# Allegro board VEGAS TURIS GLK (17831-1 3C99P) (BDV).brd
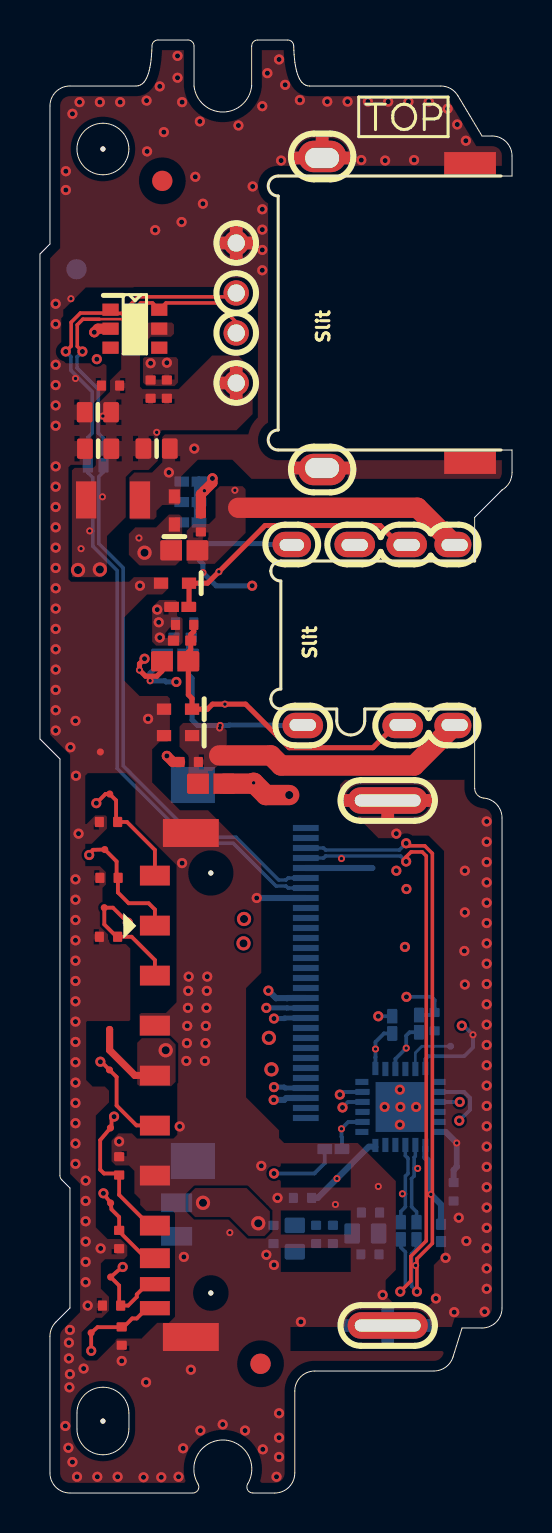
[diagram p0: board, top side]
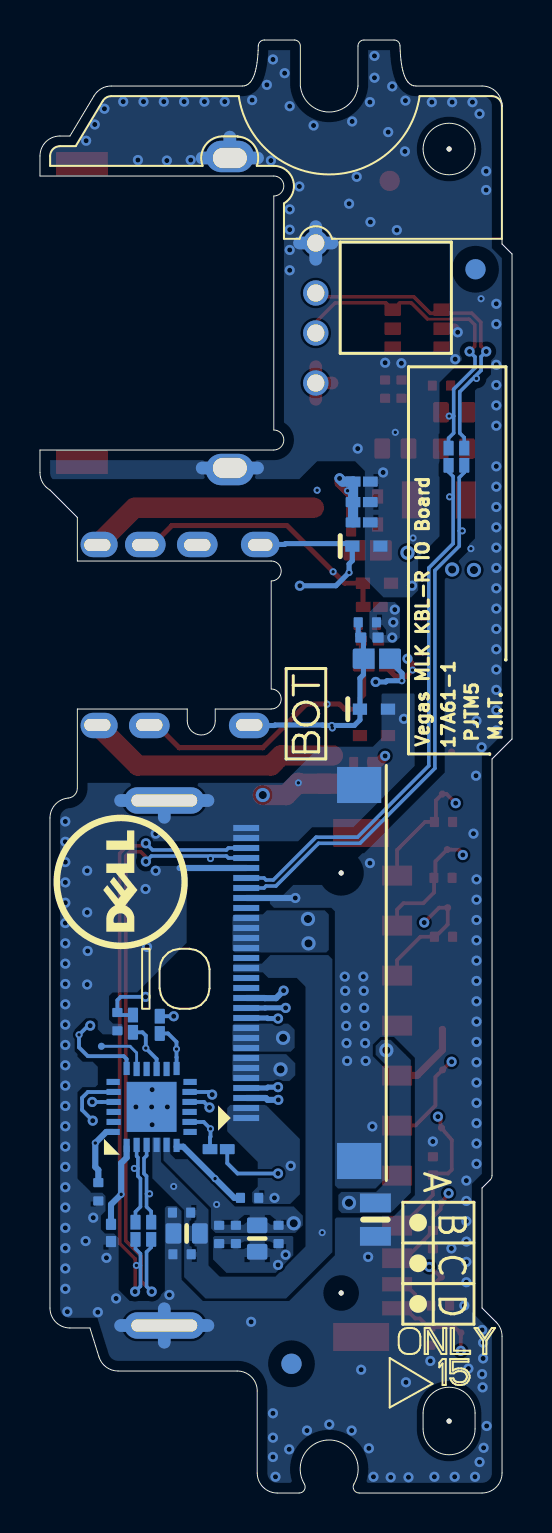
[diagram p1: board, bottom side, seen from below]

Outline 23.62 x 72.65 mm; copper layers: TOP, L2VCC, L3, L4, L5GND, BOTTOM. Coordinates in mm from the lower left corner of the outline.
Outline path: 0,61.95 0,37.7 1,36.7 1,15.87 arc(1.02,15.76) 1.09,15.66 1.5,15.25 1.5,9.25 0.79,8.54 arc(0.58,8.22) 0.5,7.84 0.5,1 arc(0.79,0.29) 1.5,0 7.65,0 arc(7.91,0.15) 7.91,0.45 arc(9.15,2.65) 10.39,0.45 arc(10.39,0.15) 10.65,0 11.75,0 arc(12.46,0.29) 12.75,1 12.75,5.1 arc(13.04,5.81) 13.75,6.1 19.71,6.1 arc(20.31,6.29) 20.67,6.8 21.12,8.25 22.12,8.25 arc(22.83,8.54) 23.12,9.25 23.12,33.75 arc(22.86,34.43) 22.21,34.75 arc(21.88,34.91) 21.75,35.24 21.75,39.2 16.25,39.2 16.25,38.6 arc(15.55,37.9) 14.85,38.6 14.85,39.2 12.05,39.2 arc(11.55,39.7) 12.05,40.2 12.05,45.6 arc(11.55,46.1) 12.05,46.6 21.75,46.6 21.75,48.78 23.12,50.15 arc(23.49,50.52) 23.62,51.02 23.62,52.15 11.92,52.15 arc(11.42,52.65) 11.92,53.15 11.92,64.85 arc(11.42,65.35) 11.92,65.85 23.62,65.85 23.62,66.85 arc(23.33,67.56) 22.62,67.85 22.12,67.85 20.91,69.86 arc(20.55,70.22) 20.05,70.35 13.49,70.35 13.38,70.36 13.28,70.4 13.19,70.45 13.11,70.53 13.04,70.62 12.98,70.71 12.93,70.82 12.89,70.94 12.85,71.07 12.81,71.21 12.78,71.36 12.76,71.53 12.73,71.72 12.72,71.91 12.7,72.13 12.7,72.36 arc(12.61,72.56) 12.4,72.65 10.89,72.65 arc(10.68,72.56) 10.59,72.35 10.59,70.35 arc(9.15,69.05) 7.71,70.35 7.71,72.35 arc(7.62,72.56) 7.41,72.65 5.9,72.65 arc(5.69,72.56) 5.6,72.36 5.59,72.1 5.58,71.86 5.56,71.65 5.53,71.45 5.5,71.27 5.46,71.11 5.42,70.97 5.38,70.85 5.33,70.74 5.28,70.64 5.21,70.55 5.13,70.47 5.03,70.4 4.92,70.36 4.81,70.35 1.5,70.35 arc(0.79,70.06) 0.5,69.35 0.5,62.45 0,61.95 ; 1.85,67.2 arc(3.15,68.5) 4.45,67.2 arc(3.15,65.9) 1.85,67.2 ; 1.85,4 arc(3.15,5.3) 4.45,4 4.45,3.2 arc(3.15,1.9) 1.85,3.2 1.85,4

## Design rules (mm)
constraint set DEFAULT: min track width 0.127, pair gap 0.102
net group SD_CLK: nets SD_CLK SD_CLK_5170
net group USB_PN2_C: nets USB_PN2_C USB_PN2_USB3
net group USB_PN5_C: nets USB_PN5_C USB_PN5_R
net group USB_PP2_C: nets USB_PP2_C USB_PP2_USB3
net group USB_PP5_C: nets USB_PP5_C USB_PP5_R
net group AUDIO-BEEP: nets AUD_PORTA_L_HPMIC1 AUD_PORTA_L_R_B AUD_PORTA_R_HPMIC1 AUD_PORTA_R_R_B JACK_PLUG JACK_PLUG_DET
net group CARD_12MIL: nets RREF SDREFG V18
net group CARD_READER_50R-MW: nets SD_CD# SD_CD_R# SD_CMD SD_WP SD_WP_5170
net group OTHER-MW: nets CR_GPIO0

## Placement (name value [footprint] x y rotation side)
AFTP201  AFTE14P-GP  [AFTE14P-75]  3.02 37.05 0 top
AFTP202  AFTE14P-GP  [AFTE14P-75]  3.22 29.26 0 top
AFTP203  AFTE14P-GP  [AFTE14P-75]  3.54 10.8 0 top
AFTP204  AFTE14P-GP  [AFTE14P-75]  3.48 21.16 0 top
AFTP205  AFTE14P-GP  [AFTE14P-75]  2.56 8.01 0 top
AFTP206  AFTE14P-GP  [AFTE14P-75]  3.53 18.25 0 top
AFTP207  AFTE14P-GP  [AFTE14P-75]  3.53 14.5 0 top
AFTP208  AFTE14P-GP  [AFTE14P-75]  3.49 34.95 0 top
AFTP209  AFTE14P-GP  [AFTE14P-75]  3.24 32.17 0 top
AFTP210  AFTE14P-GP  [AFTE14P-75]  3.48 23.18 0 top
C201  SCD1U16V2KX-3GP  [C402H22]  13.82 12.93 180 bottom
C202  SC1U10V2KX-1GP  [C402H22]  20.7 15.06 0 bottom
C203  SCD1U16V2KX-3GP  [C402H22]  14.66 12.93 180 bottom
C204  SC4D7U6D3V3KX-GP  [C603H36]  16.28 12.98 270 bottom
C205  SCD1U16V2KX-3GP  [C402H22]  16.53 14.02 270 bottom
C206  SC1U10V2KX-1GP  [C402H22]  13.13 14.76 90 bottom
C207  SC4D7U6D3V3KX-GP  [C603H36]  12.75 12.72 180 bottom
C208  SC10U10V5KX-2GP  [C805H54]  6.84 13.67 180 bottom
C301  SCD1U16V2KX-3GP  [C402H22]  6.35 55.19 180 top
C302  SC22U6D3V3MX-L1-GP  [C603H40]  2.89 54.04 270 top
C303  SC22U6D3V3MX-L1-GP  [C603H40]  2.91 52.22 270 top
C304  SC100U6D3V6MX-GP  [C1206H71]  3.66 49.66 90 top
C305  SC22U6D3V3MX-L1-GP  [C603H40]  5.84 52.22 90 top
C306  SCD1U16V2KX-3GP  [C402H22]  3.53 55.37 270 top
CARD1  SDCARD-11P-21-GP  [PSDATP-11GLBS1NN4H0]  8.55 21.5 90 top
EC201  SCD1U16V2KX-3GP  [C402H22]  16.51 11.94 270 bottom
EC202  SCD1U16V2KX-3GP  [C402H22]  11.68 12.93 180 bottom
EC203  SC6D8P50V2CN-GP  [C402H22]  3.96 16.36 180 top
EC204  SC6D8P50V2CN-GP  [C402H22]  4.09 7.85 0 top
EC205  SC6D8P50V2CN-GP  [C402H22]  3.96 12.67 0 top
EC206  SC6D8P50V2CN-GP  [C402H22]  3.45 30.76 270 top
EC207  SC6D8P50V2CN-GP  [C402H22]  3.58 9.37 270 top
EC208  SC6D8P50V2CN-GP  [C402H22]  3.43 27.81 270 top
EC209  SC6D8P50V2CN-GP  [C402H22]  3.43 33.55 270 top
EC210  SC6D8P50V2CN-GP  [C402H22]  19.75 23.57 180 bottom
EC301  SCD1U16V2KX-3GP  [C402H22]  5.54 55.19 180 top
EC402  SC680P50V2KX-2GP  [C402H22]  7.24 43.41 270 top
EC403  SC680P50V2KX-2GP  [C402H22]  7.24 43.53 90 bottom
EC404  SC680P50V2KX-2GP  [C402H22]  8.05 48.51 180 top
EC405  SC680P50V2KX-2GP  [C402H22]  7.47 36.55 270 top
ED401  AZ5125-01H-R7G-GP  [SOD-523-4H28]  6.72 49.13 180 top
ED402  AZ5125-01H-R7G-GP  [SOD-523-4H28]  6.76 45.49 270 top
ED403  AZ5125-01H-R7G-GP  [SOD-523-4H28]  7.29 47.34 90 bottom
ED404  AZ5125-01H-R7G-GP  [SOD-523-4H28]  6.91 37.87 270 top
ED405  AZ5125-01H-R7G-GP  [SOD-523-4H28]  6.91 39.19 90 bottom
ED406  AZ5125-01H-R7G-GP  [SOD-523-4H28]  6.91 39.19 270 top
EU301  AZC099-04S-2-GP  [SOT-6H58]  4.75 58.22 270 top
IOCN1  ACES-CON30-9-GP-U2  [51519-03001-W02-U2]  7.65 26 90 bottom
IUSB1  SKT-USB8-185-GP  [SKT-USB8-158161-4]  21.52 59 90 top
MIC1  AUDIO-JK554-GP  [2SJ3108-052111F]  20.75 42.9 90 top
NOREF  -  []  -201.05 -192.93 0 top
NOREF#2  -  []  -239.92 -205.64 0 top
NOREF#3  -  []  18.19 68.81 0 top
NOREF#4  *  [unnamed#2]  6.12 65.61 0 top
NOREF#5  -  [unnamed#2]  3.15 67.2 0 top
NOREF#6  *  [unnamed#2]  11.04 6.46 0 top
NOREF#7  -  []  -15.85 89 0 top
NOREF#8  -  []  -202.67 -192.25 0 top
NOREF#9  -  [unnamed#2]  3.15 3.59 0 top
NOREF#10  -  []  -202.67 -192.25 0 top
NOREF#11  *  [unnamed#2]  11.04 6.46 180 bottom
NOREF#12  -  []  10.31 38.96 90 bottom
NOREF#13  -  []  19.58 30.55 90 bottom
NOREF#14  -  []  383.93 -192.25 180 bottom
NOREF#15  -  []  374.89 -205.64 180 bottom
NOREF#16  *  [unnamed#2]  1.83 61.19 180 bottom
NOREF#17  -  []  321.64 -192.93 180 bottom
NOREF#18  -  []  5.82 59.76 180 bottom
NOREF#19  -  []  3.18 10.72 270 bottom
R201  -  [0R0402-PAD]  18.06 13.11 0 bottom
R202  6K2R2F-GP  [R402H16]  20.07 13 180 bottom
R203  -  [0R0402-PAD]  18.84 13.11 0 bottom
R204  -  [0R0402-PAD]  14.68 17.19 270 bottom
R205  -  [0R0402-PAD]  17.63 23.41 180 bottom
R206  -  [0R0402-PAD]  18.97 23.47 0 bottom
R301  -  [0R0402-PAD]  3.18 51.81 180 bottom
R302  -  [0R0402-PAD]  2.39 51.81 180 bottom
R424  -  [0R0603-PAD]  8.56 35.47 270 top
R426  -  [0R0603-PAD]  6.76 41.59 90 top
R427  -  [0R0603-PAD]  7.22 47.13 90 top
R428  10KR2J-3-GP  [R402H16]  7.11 42.62 270 top
R429  10KR2J-3-GP  [R402H16]  7.14 42.77 90 bottom
R430  -  [0R0402-PAD]  7.01 44.3 270 top
R431  -  [0R0402-PAD]  7.52 48.53 90 bottom
R432  -  [0R0402-PAD]  7.52 49.55 90 bottom
R433  -  [0R0402-PAD]  7.52 50.57 90 bottom
R434  -  [0R0603-PAD]  6.76 41.71 270 bottom
TP201  TPAD14-OP-GP  [TPAD14-OP]  20.54 22.34 180 bottom
U201  RTS5170-GR-GP  [QFN24-G2D5H40-U]  18.03 19.3 0 bottom

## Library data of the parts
AFTP201-AFTP210 = AFTE14P-75: tolerance: ZZ.AFT14.101
C201 C203 C205 C301 C306 EC201 EC202 EC301 = C402H22: tolerance: 78.10421.2FL
C202 C206 = C402H22: tolerance: 78.10523.5FL
C204 C207 = C603H36: tolerance: 78.47520.5BL
C208 = C805H54: tolerance: 78.10623.51L
C302 C303 C305 = C603H40: tolerance: 78.22610.L4L
C304 = C1206H71: tolerance: 78.10710.52L
CARD1 = PSDATP-11GLBS1NN4H0: tolerance: 062.10002.0491
EC203-EC210 = C402H22: tolerance: 78.6R874.1FL
EC402-EC405 = C402H22: tolerance: 78.68124.2FL
ED401-ED406 = SOD-523-4H28: tolerance: 75.05125.070
EU301 = SOT-6H58: tolerance: 075.09904.0A7C
IOCN1 = 51519-03001-W02-U2: tolerance: 20.K0510.030
IUSB1 = SKT-USB8-158161-4: tolerance: 022.10005.0821
MIC1 = 2SJ3108-052111F: tolerance: 022.10002.0G81
R201 = 0R0402-PAD: tolerance: ZZ.R0402.ZZZ; signal model: Graser_R201
R202 = R402H16: tolerance: 64.62015.6DL
R203 = 0R0402-PAD: tolerance: ZZ.R0402.ZZZ; signal model: Graser_R203
R204 R205 R430-R433 = 0R0402-PAD: tolerance: ZZ.R0402.ZZZ
R206 = 0R0402-PAD: tolerance: ZZ.R0402.ZZZ; signal model: Graser_R206
R301 = 0R0402-PAD: tolerance: ZZ.R0402.ZZZ; signal model: Graser_R301
R302 = 0R0402-PAD: tolerance: ZZ.R0402.ZZZ; signal model: Graser_R302
R424 R426 R427 R434 = 0R0603-PAD: tolerance: ZZ.R0603.ZZZ
R428 R429 = R402H16: tolerance: 63.10334.1DL
TP201 = TPAD14-OP: tolerance: ZZ.PAD14.001
U201 = QFN24-G2D5H40-U: tolerance: 71.05170.003

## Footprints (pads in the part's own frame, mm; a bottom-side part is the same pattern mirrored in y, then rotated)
0R0402-PAD
  custom 0.127x0.127 smd: 1(0,0.432) 2(0,-0.432)
0R0603-PAD
  custom 0.254x0.254 smd: 1(0,0.66) 2(0,-0.66)
2SJ3108-052111F
  oval 1.27x2.032 hole 0.61x1.321: 1(-4.5,7.6) 2(-4.5,2.6) 6(4.5,2.4) MS(4.5,5)
  oval 1.27x1.854 hole 0.61x1.321: 3(-4.5,0) 4(4.5,0)
  oval 1.27x1.93 hole 0.61x1.219: 5(4.5,8.15)
51519-03001-W02-U2
  rect 0.305x1.295 smd: 1(-7.25,5.65) 2(-6.75,5.65) 3(-6.25,5.65) 4(-5.75,5.65) 5(-5.25,5.65) 6(-4.75,5.65) 7(-4.25,5.65) 8(-3.75,5.65) 9(-3.25,5.65) 10(-2.75,5.65) 11(-2.25,5.65) 12(-1.75,5.65) 13(-1.25,5.65) 14(-0.75,5.65) 15(-0.25,5.65) 16(0.25,5.65) 17(0.75,5.65) 18(1.25,5.65) 19(1.75,5.65) 20(2.25,5.65) 21(2.75,5.65) 22(3.25,5.65) 23(3.75,5.65) 24(4.25,5.65) 25(4.75,5.65) 26(5.25,5.65) 27(5.75,5.65) 28(6.25,5.65) 29(6.75,5.65) 30(7.25,5.65)
  rect 1.803x2.21 smd: 31(-9.4,0) 32(9.4,0)
AFTE14P-75
  round 0.356 smd: 1(0,0)
C402H22
  custom 0.114x0.114 smd: 1(0,0.457) 2(0,-0.457)
C603H36
  custom 0.197x0.197 smd: 1(0,0.66) 2(0,-0.66)
C603H40
  custom 0.197x0.197 smd: 1(0,0.66) 2(0,-0.66)
C805H54
  rect 1.549x0.94 smd: 1(0,0.838) 2(0,-0.838)
C1206H71
  rect 1.854x1.016 smd: 1(0,1.346) 2(0,-1.346)
PSDATP-11GLBS1NN4H0
  round 0.254 hole 1.168 unplated: (-11.5,0)
  round 0.254 hole 1.651 unplated: (9.5,0)
  rect 0.991x1.499 smd: 1(6.87,2.8) 2(4.37,2.8) 3(1.87,2.8) 4(-0.63,2.8) 5(-3.13,2.8) 6(-5.63,2.8) 7(-8.13,2.8) 8(-9.76,2.8) 9(9.37,2.8)
  rect 0.711x1.499 smd: 10(-11.06,2.8) 11(-12.26,2.8)
  rect 1.397x2.794 smd: 12(11.5,1) 13(-13.7,1)
  oval 1.321x4.013 hole 0.61x3.302: 14(13.125,-8.85) 15(-13.125,-8.85)
QFN24-G2D5H40-U
  rect 0.305x0.66 smd: 1(1.25,1.987) 6(-1.25,1.987) 13(-1.25,-1.987) 18(1.25,-1.987)
  rect 0.305x0.711 smd: 2(0.75,1.962) 3(0.25,1.962) 4(-0.25,1.962) 5(-0.75,1.962) 14(-0.75,-1.962) 15(-0.25,-1.962) 16(0.25,-1.962) 17(0.75,-1.962)
  rect 0.66x0.305 smd: 7(-1.987,1.25) 12(-1.987,-1.25) 19(1.987,-1.25) 24(1.987,1.25)
  rect 0.711x0.305 smd: 8(-1.962,0.75) 9(-1.962,0.25) 10(-1.962,-0.25) 11(-1.962,-0.75) 20(1.962,-0.75) 21(1.962,-0.25) 22(1.962,0.25) 23(1.962,0.75)
  rect 2.489x2.489 smd: 25(0,0)
R402H16
  custom 0.127x0.127 smd: 1(0,0.432) 2(0,-0.432)
SKT-USB8-158161-4
  round 1.27 hole 0.864: 1(-3.5,11.7) 2(-1,11.7) 3(1,11.7) 4(3.5,11.7)
  oval 1.575x2.413 hole 1.016x1.702: 5(-7.75,7.4) 6(7.75,7.4)
  rect 1.194x2.591 smd: 7(-7.45,0) 8(7.45,0)
SOD-523-4H28
  rect 0.559x0.711 smd: 1(0,0.702) 2(0,-0.702)
SOT-6H58
  rect 0.61x0.813 smd: 1(-0.95,-1.219) 2(0,-1.219) 3(0.95,-1.219) 4(0.95,1.219) 5(0,1.219) 6(-0.95,1.219)
TPAD14-OP
  round 0.356 smd: 1(0,0)
unnamed#2
  round 1.016 smd: (0,0)

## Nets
GND: AFTP201.1 C201.2 C202.1 C203.2 C204.2 C205.2 C206.2 C207.2 C208.2 C301.2 C302.2 C303.2 C304.2 C305.2 C306.2 CARD1.3 CARD1.6 CARD1.12 CARD1.13 CARD1.14 CARD1.15 EC201.2 EC202.2 EC203.2 EC204.2 EC205.2 EC206.2 EC207.2 EC208.2 EC209.2 EC210.2 EC301.2 ED401.2 ED402.2 ED403.2 ED404.2 ED405.2 ED406.2 EU301.2 IOCN1.1 IOCN1.2 IOCN1.23 IOCN1.26 IOCN1.29 IOCN1.30 IOCN1.31 IOCN1.32 IUSB1.4 IUSB1.5 IUSB1.6 IUSB1.7 IUSB1.8 R202.2 R431.2 R432.2 R433.2 U201.25
V18: C202.2 U201.24
3D3V_CARD_S0: AFTP210.1 C201.1 C203.1 C207.1 C208.1 CARD1.4 EC202.1 U201.5
3D3V_S0: C204.1 C205.1 EC201.1 IOCN1.16 U201.4
AUD_AGND: EC402.2 EC403.2 EC404.2 EC405.2 IOCN1.3 IOCN1.13 MIC1.MS R428.2 R429.2 R430.2 R431.1 R432.1 R433.1
AUD_PORTA_L_HPMIC1: EC403.1 ED405.1 MIC1.1 R429.1 R434.2
AUD_PORTA_L_R_B: IOCN1.12 R434.1
AUD_PORTA_R_HPMIC1: EC402.1 ED406.1 MIC1.2 R426.2 R428.1
AUD_PORTA_R_R_B: IOCN1.11 R426.1
CR_GPIO0: TP201.1 U201.17
JACK_PLUG: ED403.1 IOCN1.4 MIC1.5
JACK_PLUG_DET: ED402.1 MIC1.6 R430.1
RING2_HPMIC1: EC405.1 ED404.1 MIC1.3 R424.2
RING2_R: IOCN1.5 IOCN1.6 IOCN1.7 R424.1
RREF: R202.1 U201.1
SD_CD#: R205.2 U201.13
SD_CD_R#: AFTP203.1 CARD1.10 EC207.1 R205.1
SD_CLK: AFTP204.1 CARD1.5 EC210.1 R206.2
SD_CLK_5170: R206.1 U201.15
SD_CMD: AFTP202.1 CARD1.2 EC208.1 U201.18
SD_D0: AFTP206.1 CARD1.7 EC203.1 U201.11
SD_D1: AFTP207.1 CARD1.8 EC205.1 U201.10
SD_D2: AFTP208.1 CARD1.9 EC209.1 U201.21
SD_D3: AFTP209.1 CARD1.1 EC206.1 U201.20
SD_WP: AFTP205.1 CARD1.11 EC204.1 R204.1
SD_WP_5170: R204.2 U201.8
SDREFG: C206.1 U201.6
SLEEVE_HPMIC1: EC404.1 MIC1.4 R427.2
SLEEVE_R: ED401.1 IOCN1.8 IOCN1.9 IOCN1.10 R427.1
USB20_VCCA: C301.1 C302.1 C303.1 C304.1 C305.1 C306.1 EC301.1 EU301.5 IOCN1.18 IOCN1.19 IOCN1.20 IOCN1.21 IUSB1.1
USB_PN2_C: IOCN1.25 R301.2
USB_PN2_USB3: EU301.6 IUSB1.2 R301.1
USB_PN5_C: IOCN1.28 R203.1
USB_PN5_R: R203.2 U201.2
USB_PP2_C: IOCN1.24 R302.2
USB_PP2_USB3: EU301.1 IUSB1.3 R302.1
USB_PP5_C: IOCN1.27 R201.1
USB_PP5_R: R201.2 U201.3

Pads without a net: EU301 3 4; IOCN1 14 15 17 22; U201 7 9 12 14 16 19 22 23

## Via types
v1: diameter 0.356, hole 0.178, TOP to BOTTOM, 32 vias
v2: diameter 0.711, hole 0.406, TOP to BOTTOM, 11 vias
v3: diameter 0.508, hole 0.254, TOP to BOTTOM, 225 vias

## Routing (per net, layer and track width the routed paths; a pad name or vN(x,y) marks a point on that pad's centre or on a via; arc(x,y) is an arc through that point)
GND: length 83.6
  TOP w0.508: EU301.2 2.9,58.22 v3(2.72,58.04)
  TOP w0.635: 15.22,34.63 CARD1.14 ; CARD1.14 19.58,34.63 ; CARD1.14 17.4,33.79 ; IUSB1.6 15.5,66.75 ; IUSB1.6 12.74,66.75 ; IUSB1.6 14.12,67.79 ; 12.74,51.25 IUSB1.5 15.5,51.25 ; 9.82,61.69 IUSB1.4 ; IUSB1.4 10.63,62.5 ; IUSB1.4 9.01,62.5 ; IUSB1.4 9.82,63.31
  L3 w0.635: 15.22,8.38 CARD1.15 ; CARD1.15 17.4,7.54 ; CARD1.15 17.4,9.21 ; CARD1.15 19.58,8.38 ; CARD1.14 17.4,35.46 ; CARD1.14 17.4,33.79 ; CARD1.14 15.22,34.63 ; CARD1.14 19.58,34.63 ; IUSB1.6 15.5,66.75 ; IUSB1.6 14.12,67.79 ; IUSB1.6 12.74,66.75 ; 9.82,61.69 IUSB1.4 ; IUSB1.4 9.01,62.5 ; IUSB1.4 10.63,62.5 ; IUSB1.4 9.82,63.31 ; 12.74,51.25 IUSB1.5 15.5,51.25
  L4 w0.635: IUSB1.4 10.63,62.5 ; IUSB1.4 9.82,61.69 ; IUSB1.4 9.82,63.31 ; IUSB1.4 9.01,62.5 ; IUSB1.6 14.12,67.79 ; IUSB1.6 15.5,66.75 ; IUSB1.6 12.74,66.75 ; 19.58,34.63 CARD1.14 17.4,33.79 ; CARD1.15 17.4,9.21 ; CARD1.15 17.4,7.54 ; CARD1.15 15.22,8.38 ; CARD1.15 19.58,8.38 ; 12.74,51.25 IUSB1.5 15.5,51.25
  BOTTOM w0.305: IOCN1.23 v3(10.85,29.75) ; IOCN1.26 16.64,31.25
  BOTTOM w0.635: 9.82,61.69 IUSB1.4 ; IUSB1.4 9.82,63.31 ; IUSB1.4 9.01,62.5 ; IUSB1.4 10.63,62.5 ; 12.74,66.75 IUSB1.6 ; IUSB1.6 14.12,67.79 ; IUSB1.6 15.5,66.75 ; 17.4,33.79 CARD1.14 ; CARD1.14 19.58,34.63 ; CARD1.14 15.22,34.63 ; CARD1.15 17.4,9.21 ; CARD1.15 19.58,8.38 ; CARD1.15 17.4,7.54 ; CARD1.15 15.22,8.38 ; 12.74,51.25 IUSB1.5 15.5,51.25
  vias: v1(1.55,59.71) v1(5.84,53.03) v3(0.79,59.46) v3(0.79,58.44) v3(0.79,56.41) v3(0.79,55.4) v3(0.79,54.38) v3(0.79,53.36) v3(0.79,51.33) v3(0.79,50.32) v3(0.79,49.3) v3(0.79,48.28) v3(0.79,47.27) v3(0.79,46.25) v3(0.79,45.24) v3(0.79,44.22) v3(0.79,43.2) v3(0.79,42.19) v3(0.79,41.17) v3(0.79,40.16) v3(0.79,39.14) v3(0.79,38.12) v3(1.29,66.09) v3(1.29,65.15) v3(1.27,3.35) v3(1.5,8.15) v3(1.45,7.52) v3(1.45,6.73) v3(1.5,5.94) v3(1.47,5.28) v3(1.42,2.26) v3(1.52,37.29) v3(1.63,68.96) v3(1.63,1.55) v3(1.78,38.61) v3(1.78,30.68) v3(1.78,29.67) v3(1.78,28.65) v3(1.78,27.63) v3(1.78,26.62) v3(1.78,25.6) v3(1.78,24.59) v3(1.78,23.57) v3(1.78,22.55) v3(1.78,21.54) v3(1.78,20.52) v3(1.78,19.51) v3(1.78,18.49) v3(1.78,17.47) v3(1.78,16.46) v3(1.8,35.86) v3(1.85,0.81) v3(1.98,69.54) v3(1.93,32.97) v3(2.18,6.22) v3(2.29,15.62) v3(2.29,14.6) v3(2.29,13.59) v3(2.29,12.57) v3(2.29,11.56) v3(2.29,10.54) v3(2.39,9.37) v3(2.84,56.69) v3(2.87,0.81) v3(3,69.54) v3(3.03,12.23) v3(3.89,0.81) v3(3.96,17.58) v3(4.01,69.54) v3(4.09,6.6) v3(5,45.36) v3(5.18,0.79) v3(5.33,69.62) v3(5.36,67.08) v3(5.31,5.54) v3(5.41,38.71) v3(5.54,56.49) v3(5.77,63.14) v3(5.99,70.33) v3(6.07,0.79) v3(6.2,68.05) v3(6.35,56.51) v3(6.45,51.03) v3(6.88,71.86) v3(6.88,70.76) v3(6.99,18.33) v3(6.93,0.81) v3(7.09,63.55) v3(7.11,69.54) v3(7.11,31.49) v3(7.2,11.8) v3(7.16,2.23) v3(7.37,23.36) v3(7.35,22.49) v3(7.32,21.6) v3(7.44,25.82) v3(7.42,25.11) v3(7.4,24.26) v3(7.55,6.16) v3(7.77,65.81) v3(7.72,52.22) v3(8,68.58) v3(8.03,3.12) v3(8.15,64.46) v3(8.3,23.36) v3(8.28,22.49) v3(8.25,21.6) v3(8.37,25.82) v3(8.35,25.11) v3(8.33,24.26) v3(9.14,3.43) v3(9.93,68.38) v3(10.26,3.12) v3(10.64,65.33) v3(11.07,16.36) v3(11.12,69.34) v3(11.12,64.18) v3(11.12,63.17) v3(11.12,62.15) v3(11.12,61.14) v3(11.15,2.18) v3(11.38,70.99) v3(11.33,11.91) v3(11.71,11.4) v3(11.89,14.76) v3(11.84,0.81) v3(11.96,71.68) v3(11.96,3.99) v3(11.96,2.77) v3(11.96,1.8) v3(12.06,66.62) v3(12.27,70.41) v3(13,69.65) v3(13.06,8.56) v3(14.38,69.57) v3(15.39,69.57) v3(16.08,66.65) v3(16.41,69.57) v3(17.14,9.9) v3(17.27,66.62) v3(17.25,19.3) v3(17.42,69.57) v3(17.83,32.97) v3(17.83,31.11) v3(18.01,20.17) v3(18.03,19.3) v3(18.01,18.41) v3(18.26,27.3) v3(18.34,30.2) v3(18.44,69.57) v3(18.72,66.65) v3(18.82,19.3) v3(19.46,69.57) v3(19.81,9.73) v3(20.29,11.76) v3(20.4,69.21) v3(20.73,9.04) v3(20.88,68.43) v3(20.95,13.77) v3(21.26,31.11) v3(21.26,29.03) v3(21.23,27.1) v3(21.26,25.42) v3(21.31,67.61) v3(21.34,12.6) v3(22.25,9.07) v3(22.35,33.58) v3(22.35,32.56) v3(22.35,31.55) v3(22.35,30.53) v3(22.35,29.51) v3(22.35,28.5) v3(22.35,27.48) v3(22.35,26.47) v3(22.35,25.45) v3(22.35,24.43) v3(22.35,23.42) v3(22.35,22.4) v3(22.35,21.39) v3(22.35,20.37) v3(22.35,19.35) v3(22.35,18.34) v3(22.35,17.32) v3(22.35,16.31) v3(22.35,15.29) v3(22.35,14.27) v3(22.35,13.26) v3(22.35,12.24) v3(22.35,11.23) v3(22.35,10.21)
V18: length 3.1
  BOTTOM w0.305: U201.24 20.3,18.05 v1(20.85,17.5) 20.85,16.31 20.7,16.15 C202.2
3D3V_CARD_S0: length 3.9
  TOP w0.356: AFTP210.1 3.48,22.14 4.75,20.88 5.8,20.88
  vias: v1(14.78,14.43) v2(6.29,22.14) v2(8.16,14.51) v2(10.92,13.49)
3D3V_S0:
  vias: v1(9.5,13.02) v1(16.93,15.33)
AUD_AGND: length 9.2
  TOP w0.508: v3(8.63,50.73) 8.63,50.51 v1(8.23,50.11) 8.05,49.93 EC404.2 ; v3(6.35,36.85) 6.65,36.55 EC405.2
  BOTTOM w0.305: v3(11.43,25.12) 11.81,24.74 12.36,24.74 12.37,24.75 IOCN1.13 ; v3(11.69,19.66) 12.23,19.66 12.32,19.75 IOCN1.3
  BOTTOM w0.508: v3(8.63,50.73) 8.47,50.57 R433.1 7.95,50.56 R432.1 R431.1
  vias: v3(5.87,44.17) v3(5.94,43.53) v3(5.99,42.77)
AUD_PORTA_L_HPMIC1: length 10.8
  BOTTOM w0.254: 7.44,41.71 7.44,40.91 7.61,40.74 ED405.1 7.61,38.66 7.89,38.38 v1(9.02,38.38) 9.45,38.38 9.47,38.4 11.85,38.4 11.88,38.37 13.12,38.37 MIC1.1 ; 7.44,41.71 7.44,42.64 R429.1 7.7,42.9 EC403.1 ; 7.44,41.71 R434.2
AUD_PORTA_L_R_B: length 23.8
  L3 w0.254: v3(11.33,24.26) 11.86,24.26 12.12,24.51 12.12,31.44 7.47,36.09 7.47,39.91 v3(6.82,40.55)
  BOTTOM w0.254: IOCN1.12 12.36,24.25 12.35,24.26 v3(11.33,24.26) ; v3(6.82,40.55) 6.32,40.55 6.26,40.61 v1(5.51,40.61) 5.5,40.62 5.5,40.98 6.1,41.59 R434.1
AUD_PORTA_R_HPMIC1: length 16.4
  TOP w0.254: EC402.1 7.7,43.08 7.54,42.92 R428.1 7.54,42.16 7.42,42.04 R426.2 7.42,39.91 7.61,39.72 ED406.1 8.38,39.19 8.63,39.44 v1(9.25,39.44) 10.29,39.44 12.47,37.27 16.66,37.27 17.79,38.4 MIC1.2
AUD_PORTA_R_R_B: length 26.5
  TOP w0.254: R426.1 6.1,41.09 5.85,40.84 5.28,40.84 v1(4.98,41.15) 4.98,41.46 v3(5.23,41.71)
  L3 w0.254: v3(11.71,23.72) 12.12,23.72 12.62,24.23 12.62,31.65 8.08,36.2 8.08,40.03 6.39,41.71 v3(5.23,41.71)
  BOTTOM w0.254: IOCN1.11 12.25,23.75 12.22,23.72 v3(11.71,23.72)
CR_GPIO0: length 2.6
  BOTTOM w0.14: TP201.1 19.11,22.34 18.78,22.01 U201.17
JACK_PLUG: length 40
  L3 w0.254: v3(11.71,20.29) 13.03,20.29 15.67,22.93 15.67,33.03 10.62,38.09 v3(10.62,45.36)
  BOTTOM w0.254: v3(11.71,20.29) 12.22,20.29 12.26,20.25 IOCN1.4 ; v3(10.62,45.36) 8.81,45.36 v1(8.15,46.02) 8.15,46.45 7.99,46.62 ED403.1 8.12,47.47 11.34,47.47 11.38,47.43 12.57,47.43 MIC1.5
JACK_PLUG_DET: length 13.7
  TOP w0.254: MIC1.6 17.99,47.4 17.02,48.37 11.26,48.37 v1(8.95,46.06) 8.38,45.49 ED402.1 7.46,45.49 7.46,44.3 R430.1
RING2_HPMIC1: length 12.8
  TOP w1.016: 8.97,36.88 11.56,36.88 12.06,36.38 18.73,36.38 MIC1.3
  vias: v1(8.99,38.25)
RING2_R: length 20.1
  TOP w1.016: R424.1 10.65,35.47 v1(10.69,35.51) 11.3,34.9 v2(12.47,34.9)
  L3 w1.016: v2(11.58,21.18) 12.57,21.18 12.62,21.23 12.71,21.23 14.78,23.3 14.78,32.59 v2(12.47,34.9)
RREF: length 4.2
  BOTTOM w0.305: U201.1 19.28,16.77 19.56,16.5 v1(19.56,14.93) 20.07,14.43 R202.1
SD_CD#: length 2.3
  BOTTOM w0.191: R205.2 17.21,22.98 16.79,22.55 v1(16.79,22.2) 16.79,21.78 16.78,21.78 U201.13
SD_CD_R#: length 35.6
  TOP w0.191: v3(4.14,11.3) 4.11,11.3 AFTP203.1 3.96,10.37 3.96,9.45 EC207.1 4.41,9.37 4.84,9.8 4.84,9.93 5.36,10.44 CARD1.10
  L3 w0.165: v3(16.93,23.84) 16.93,22.38 15.61,21.06 15.61,17.77 14.68,16.84 9.68,16.84 6.84,14 6.84,13.72 7.7,12.86 7.7,12.63 7.47,12.39 7.23,12.39 6.36,13.26 6.1,13.26 5.91,13.07 5.91,12.78 6.72,11.97 6.72,11.74 6.49,11.5 6.25,11.5 5.43,12.33 5.17,12.33 4.94,12.1 3.56,12.1 3.36,11.9 3.36,10.24 3.53,10.08 3.97,10.08 4.14,10.24 v3(4.14,11.3)
  BOTTOM w0.191: R205.1 16.93,23.84 v3(16.93,23.84)
SD_CLK: length 35.4
  TOP w0.191: CARD1.5 5.79,18.37 5.8,18.38 4.83,18.38 3.83,19.37 3.83,20.8 AFTP204.1 3.07,21.56 v3(3.02,21.56)
  L3 w0.165: v3(18.34,24.81) 18.34,26.42 18.06,26.7 16.57,26.7 16.41,26.53 16.41,26.17 16.57,26 17.5,26 17.66,25.83 17.66,25.5 17.5,25.34 16.69,25.34 16.41,25.05 16.41,22.65 12.41,18.66 10.23,18.66 9.91,18.98 6.52,18.98 5.86,19.64 5.61,19.64 5.16,19.19 4.88,19.19 4.69,19.38 4.69,19.66 5.12,20.08 5.12,20.38 3.94,21.56 v3(3.02,21.56)
  BOTTOM w0.191: v3(18.34,24.81) 19.58,24.81 19.75,24.64 EC210.1 19.62,23.9 R206.2
SD_CLK_5170: length 2.5
  BOTTOM w0.191: U201.15 17.78,21.7 v1(18.33,22.25) 18.33,22.87 18.49,23.04 R206.1
SD_CMD: length 39.2
  TOP w0.191: v3(4.39,28.52) 3.65,29.26 AFTP202.1 3.22,28.43 3.83,27.81 EC208.1 4.59,27.81 5.75,26.65 CARD1.2
  L4 w0.165: v3(4.39,28.52) 4.39,23.23 9.62,18.01 15.8,18.01 16.15,17.65 18.39,17.65 19.71,18.97 19.71,21.97 v3(21.11,23.37)
  BOTTOM w0.191: U201.18 19.28,21.7 19.43,21.84 21.23,21.84 21.67,22.28 v1(21.67,22.91) 21.21,23.37 v3(21.11,23.37)
SD_D0: length 37.4
  TOP w0.191: CARD1.7 5.5,13.37 3.96,14.9 EC203.1 3.89,15.98 3.2,15.98 3.01,16.17 3.01,17.64 AFTP206.1 3.58,18.26 3.58,18.69 v3(3.71,18.82)
  L3 w0.165: v3(3.71,18.82) 4.21,19.32 4.21,20.62 4.01,20.82 3.06,20.82 2.9,20.66 2.9,18.23 3.09,18.04 4.54,18.04 4.71,17.87 4.71,16.9 4.9,16.7 5.24,16.7 5.4,16.87 5.4,18.59 5.59,18.78 5.96,18.78 6.12,18.62 6.12,16.58 6.29,16.42 6.62,16.42 6.78,16.58 6.78,17.68 6.95,17.84 8.26,17.84 8.46,18.04 8.46,18.31 8.62,18.48 8.95,18.48 9.12,18.31 9.12,18.04 9.31,17.84 10.87,17.84 11.22,18.19 11.88,18.19 12.23,17.84 12.93,17.84 13.09,18.01 13.09,18.64 13.26,18.8 13.65,18.8 13.81,18.64 13.81,18.01 13.98,17.84 14.35,17.84 14.53,18.02 14.53,19.45 v3(15,19.92)
  BOTTOM w0.191: U201.11 15.14,20.05 v3(15,19.92)
SD_D1: length 38.2
  TOP w0.191: v3(3.17,14.98) AFTP207.1 3.58,14.18 3.96,13.8 EC205.1 3.96,13.08 5.28,11.76 5.8,11.76 5.78,11.74 CARD1.8
  L3 w0.165: v3(3.17,14.98) 3.17,16.85 3.33,17 3.88,17 4.05,16.82 4.05,16.47 4.32,16.2 5.68,16.2 5.85,16.03 5.85,15.7 5.68,15.54 4.22,15.54 4.05,15.37 4.05,14.3 3.86,14.11 3.01,14.11 2.82,13.92 2.82,13.64 3.01,13.45 3.86,13.45 4.05,13.26 4.05,12.79 4.25,12.59 4.52,12.59 4.71,12.79 4.71,14.78 4.91,14.98 5.19,14.98 5.38,14.79 5.38,13.93 5.57,13.73 5.85,13.73 6.04,13.93 6.04,14.79 6.24,14.98 7.09,14.98 7.47,15.36 7.47,15.64 7.14,15.96 7.14,16.24 7.33,16.43 7.61,16.43 7.93,16.1 8.21,16.1 8.4,16.3 8.4,16.57 8.07,16.9 8.07,17.17 8.27,17.36 8.54,17.36 8.87,17.04 9.14,17.04 9.42,17.32 14.5,17.32 15.14,17.96 v3(15.14,19.28)
  BOTTOM w0.191: U201.10 15.41,19.55 v3(15.14,19.28)
SD_D2: length 39.6
  TOP w0.191: v3(2.82,34.49) 3.28,34.95 AFTP208.1 3.81,34.63 3.81,33.63 EC209.1 4.35,33.55 5.75,32.15 CARD1.9
  L4 w0.165: v3(21.01,19.55) 18.62,17.17 15.9,17.17 15.54,17.52 9.32,17.52 3.65,23.19 3.65,33.66 v3(2.82,34.49)
  BOTTOM w0.191: v3(21.01,19.55) 20.53,19.55 U201.21
SD_D3: length 39.8
  TOP w0.191: CARD1.1 5.75,29.17 5.44,29.49 4.44,29.49 3.9,30.03 3.9,30.75 EC206.1 3.83,30.83 3.83,31.58 AFTP209.1 2.65,32.16 2.46,31.97 v3(2.46,31.9)
  L4 w0.165: v3(20.98,18.62) 19,16.64 15.52,16.64 15.11,17.04 9.13,17.04 3.18,22.99 3.18,31.18 v3(2.46,31.9)
  BOTTOM w0.191: v3(20.98,18.62) 21.51,19.15 21.51,19.76 21.22,20.05 U201.20
SD_WP: length 35
  TOP w0.191: v3(2.56,7.11) AFTP205.1 2.88,8.29 4.08,8.29 EC204.1 4.19,8.3 4.61,8.73 4.84,8.73 5.36,9.24 CARD1.11
  L3 w0.165: v3(11.71,15.98) 11.71,15.33 11.54,15.16 11.3,15.16 10.83,15.63 10.56,15.63 10.36,15.44 10.36,15.17 10.83,14.69 10.83,14.42 10.49,14.08 10.22,14.08 9.73,14.57 9.46,14.57 9.27,14.37 9.27,14.1 9.75,13.61 9.75,13.34 9.56,13.14 9.29,13.14 8.8,13.63 8.53,13.63 8.33,13.44 8.33,13.17 8.82,12.68 8.82,12.17 6.9,10.25 6.55,10.25 5.34,11.46 5.07,11.46 4.88,11.27 4.88,10.99 6.26,9.61 6.26,9.19 5.64,8.57 5.3,8.57 4.85,9.02 4.85,9.46 4.69,9.63 4.36,9.63 4.19,9.46 4.19,9.02 4,8.82 3.09,8.82 2.87,8.61 2.87,8.23 3.04,8.06 3.92,8.06 4.09,7.9 4.09,7.28 3.92,7.11 v3(2.56,7.11)
  BOTTOM w0.191: v3(11.71,15.98) 13.73,15.98 14.25,16.49 R204.1
SD_WP_5170: length 2.2
  BOTTOM w0.191: R204.2 15.11,17.78 15.09,17.81 v1(15.09,18.21) 15.43,18.55 U201.8
SDREFG: length 4.3
  BOTTOM w0.305: C206.1 13.89,14.76 v1(14.86,15.72) 16.45,17.32 U201.6
SLEEVE_HPMIC1: length 11.6
  TOP w1.016: MIC1.4 18.89,49.26 9.92,49.26
  vias: v1(9.75,50.14)
SLEEVE_R: length 30.7
  L3 w1.016: v2(5.23,47.01) 7.98,47.01 9.47,45.52 9.47,36.06 13.51,32.02 13.51,23.86 12.51,22.86 12.48,22.86 12.38,22.76 v2(11.45,22.76)
  vias: v1(4.95,47.75)
USB20_VCCA: length 2.4
  TOP w0.635: 9.01,55.5 IUSB1.1 ; IUSB1.1 9.82,54.69 ; IUSB1.1 9.82,56.31
  vias: v1(2.06,47.22) v2(1.9,46.15) v2(3,46.18) v2(10.18,27.48) v2(10.21,28.7)
USB_PN2_C: length 27.3
  BOTTOM w0.178: 2.95,49.81 2.95,47.47 4.17,46.25 4.17,36.36 7.73,32.79 9.8,32.79 11.94,30.65 12.31,30.65 12.41,30.75 IOCN1.25 ; 2.95,49.81 2.95,50.82 3.18,51.05 R301.2 ; 2.95,49.81 v1(3.12,49.81)
USB_PN2_USB3: length 16.8
  TOP w0.127: 2.96,58.69 2.96,58.69 4.23,58.69
  TOP w0.178: v3(2.12,57.08) 1.87,57.33 1.87,58.41 2.15,58.69 2.96,58.69 ; IUSB1.2 9.82,58.54 8.86,59.5 6.31,59.5 EU301.6 5.63,59.5 5.04,59.5 4.23,58.69
  BOTTOM w0.178: v1(3.15,53.85) 2.92,53.85 ; 2.92,53.85 2.92,55.19 1.85,56.25 1.85,56.81 v3(2.12,57.08) ; 2.92,53.85 2.92,53 3.18,52.74 R301.1
USB_PN5_C: length 32
  TOP w0.178: v3(18.86,10.07) 18.86,11.71 19.63,12.48 19.63,31.98 19.25,32.36 18.45,32.36 v3(18.32,32.48)
  BOTTOM w0.178: R203.1 18.84,12.22 18.59,11.97 18.59,11.38 ; v1(18.8,11.38) 18.59,11.38 ; 18.59,11.38 18.59,10.34 v3(18.86,10.07) ; IOCN1.28 14.19,32.25 14.29,32.15 17.99,32.15 v3(18.32,32.48)
USB_PN5_R: length 4.2
  BOTTOM w0.178: R203.2 18.84,14.06 18.59,14.31 18.59,15.72 18.72,15.84 18.72,16.23 ; 18.72,16.23 v1(18.9,16.23) ; 18.72,16.23 18.72,16.78 18.78,16.84 U201.2
USB_PP2_C: length 27.8
  BOTTOM w0.178: 2.64,48.11 2.64,47.34 3.86,46.12 3.86,36.23 7.61,32.49 9.68,32.49 11.81,30.35 12.31,30.35 12.41,30.25 IOCN1.24 ; 2.64,48.11 2.64,50.77 2.39,51.02 R302.2 ; 2.64,48.11 v1(2.49,48.11)
USB_PP2_USB3: length 16.2
  TOP w0.178: IUSB1.3 9.63,59.81 4.91,59.81 4.08,58.98 3.72,58.98 EU301.1 3.36,58.99 2.02,58.99 1.56,58.54 1.56,57.35 v3(1.29,57.08)
  BOTTOM w0.178: v3(1.29,57.08) 1.55,56.82 1.55,56.13 1.86,55.81 ; 1.86,55.81 2.62,55.06 2.62,53 2.39,52.77 R302.1 ; 1.86,55.81 v1(1.78,55.73)
USB_PP5_C: length 31.9
  TOP w0.178: v3(18.32,31.57) 18.32,31.81 18.57,32.05 19.13,32.05 19.33,31.85 19.33,12.61 18.56,11.84 18.56,10.6 v3(18.03,10.07)
  BOTTOM w0.178: 15.09,31.85 14.29,31.85 14.19,31.75 IOCN1.27 ; 15.09,31.85 v1(15.09,31.72) ; 15.09,31.85 18.05,31.85 v3(18.32,31.57) ; v3(18.03,10.07) 18.29,10.33 18.29,12.05 18.06,12.28 R201.1
USB_PP5_R: length 4.2
  BOTTOM w0.178: U201.3 18.28,16.87 18.41,16.74 18.41,15.97 18.29,15.84 18.29,14.96 ; v1(18.14,14.96) 18.29,14.96 ; 18.29,14.96 18.29,14.31 18.06,14.08 R201.2

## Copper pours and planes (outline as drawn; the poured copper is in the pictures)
GND on TOP: 5.33,55.35 5.16,55.52 5.16,56.72 5.23,56.79 6.81,56.79 6.91,56.69 6.91,55.52 6.73,55.35 ; 2 cut-outs
GND on TOP: outline of 195 points within 0.51,0.51 23.11,72.14 ; 18 cut-outs
GND on BOTTOM: outline of 223 points within 0.51,0.51 23.11,72.14 ; 8 cut-outs
GND on BOTTOM: 11.72,11.01 10.95,11.78 10.95,12.8 11,12.85 14.88,12.85 14.96,12.77 14.96,11.68 14.28,11.01 ; 6 cut-outs
GND on BOTTOM: 16.79,18.08 16.79,20.57 19.3,20.57 19.3,18.08
GND on BOTTOM: 11.1,14.45 10.62,14.93 10.62,17.7 12.32,19.4 14.1,19.4 14.25,19.25 14.25,18.08 12.72,16.56 12.72,15.31 13,15.04 13,14.55 12.9,14.45 ; 1 cut-out
GND on L2VCC: outline of 136 points within 0.51,0.51 23.11,72.14
GND on L3: 4.85,23.21 4.85,28.17 5.1,28.42 5.99,28.42 7.52,26.9 10.44,26.9 10.82,26.52 10.82,26.01 10.18,25.37 10.18,21.06 10.06,20.93 7.14,20.93
GND on L3: outline of 149 points within 0.51,0.51 23.11,72.14 ; 1 cut-out
GND on L4: outline of 187 points within 0.51,0.51 23.11,72.14
GND on L5GND: outline of 122 points within 0.51,0.51 23.11,72.14 ; 1 cut-out
3D3V_CARD_S0 on TOP: 10.44,12.85 9.49,13.8 7.76,13.8 7.42,14.14 7.42,14.9 7.77,15.25 10.34,15.25 11.5,14.08 11.5,13.12 11.23,12.85
3D3V_CARD_S0 on TOP: 4.97,20.34 4.86,20.45 4.86,22.5 5.1,22.74 6.47,22.74 6.79,22.42 6.79,20.56 6.57,20.34
3D3V_CARD_S0 on BOTTOM: 10.85,13 10.46,13.38 10.46,13.87 10.92,14.32 13.87,14.32 16.23,16.69 16.84,16.69 17.1,16.95 17.1,17.74 17.14,17.77 17.43,17.77 17.44,17.76 17.44,16.63 15.06,14.25 15.06,13.23 14.83,13 ; 4 cut-outs
3D3V_CARD_S0 on BOTTOM: 6.08,13.99 5.06,15.01 5.06,21.65 6.07,22.66 6.53,22.66 6.82,22.36 6.82,21.91 6.14,21.23 6.14,15.72 6.8,15.05 8.54,15.05 8.69,14.9 8.69,14.16 8.52,13.99
3D3V_S0 on BOTTOM: 11.3,9.73 8.99,12.04 8.99,26.69 9.19,26.9 12.09,26.9 12.52,26.47 13.91,26.47 13.95,26.42 13.95,26.07 13.92,26.03 12.47,26.03 12.19,25.75 10.77,25.75 10.34,25.32 10.34,12.32 11.84,10.82 14.63,10.82 15.19,11.38 15.19,14.17 17.56,16.54 17.56,17.73 17.61,17.78 17.97,17.78 18,17.75 18,15.74 16.41,14.15 16.41,10.79 15.34,9.73 ; 4 cut-outs
AUD_AGND on TOP: 5.82,42.37 5.61,42.57 5.61,44.3 5.97,44.65 6.78,44.65 6.86,44.58 6.86,43.86 6.93,43.79 7.06,43.79 7.14,43.71 7.14,42.52 6.98,42.37 ; 2 cut-outs
AUD_AGND on BOTTOM: 5.87,42.52 5.61,42.77 5.61,44.3 5.87,44.55 6.63,44.55 7.14,44.04 7.14,42.77 6.88,42.52 ; 2 cut-outs
AUD_AGND on L2VCC: 11.56,19.14 10.83,19.86 10.83,25.19 11.49,25.85 11.49,31.78 8.61,34.66 7.09,34.66 6.06,35.69 6.06,37.05 6.2,37.2 6.58,37.2 6.92,37.54 6.92,40.06 6.63,40.35 5.13,40.35 4.71,40.77 4.71,43.66 5.51,44.46 6.3,44.46 6.87,45.03 6.87,45.9 6.48,46.29 5.03,46.29 4.25,47.07 4.25,48.05 4.5,48.3 5.84,48.3 6.21,48.66 6.21,48.97 6.25,49.01 7.09,49.01 7.45,49.37 7.45,50.67 7.98,51.19 9.5,51.19 10.36,50.33 22.58,50.33 21.24,48.99 21.24,47.11 12.05,47.11 11.08,46.36 11.54,45.23 11.54,40.57 11.08,39.44 12.05,38.69 14.34,38.69 14.34,38.6 15.55,37.39 16.76,38.6 16.76,38.69 21.24,38.69 21.24,35.83 15.11,35.83 14.49,35.21 14.49,34.62 15.89,33.22 15.89,22.86 12.16,19.14
AUD_AGND on L4: 6.93,40.05 6.63,40.36 5.13,40.36 4.7,40.79 4.7,43.66 5.51,44.47 6.3,44.47 6.86,45.03 6.86,45.9 6.48,46.28 5.05,46.28 4.24,47.09 4.24,48.06 4.5,48.31 5.84,48.31 6.2,48.66 6.2,48.97 6.25,49.02 7.09,49.02 7.44,49.38 7.44,50.67 7.98,51.2 9.5,51.2 10.41,50.29 22.38,50.29 22.38,50.13 21.24,48.99 21.24,47.11 12.05,47.11 11.08,46.36 11.54,45.23 11.54,40.57 11.08,39.44 12.05,38.69 14.34,38.69 14.34,38.6 15.55,37.39 16.76,38.6 16.76,38.69 21.24,38.69 21.24,35.84 15.11,35.84 14.48,35.2 14.48,34.64 15.87,33.25 15.87,22.86 12.42,19.4 11.3,19.4 10.82,19.89 10.82,25.2 11.51,25.88 11.51,31.77 8.61,34.67 7.09,34.67 6.07,35.69 6.07,37.06 6.2,37.18 6.58,37.18 6.93,37.54
AUD_AGND on L5GND: 11.66,35.83 9.78,37.7 7.11,37.7 6.92,37.9 6.92,40.06 6.63,40.35 5.13,40.35 4.71,40.77 4.71,43.66 5.51,44.46 6.3,44.46 6.87,45.03 6.87,45.9 6.48,46.29 5.03,46.29 4.25,47.07 4.25,48.05 4.5,48.3 5.84,48.3 6.21,48.66 6.21,48.97 6.25,49.01 7.09,49.01 7.45,49.37 7.45,50.67 7.98,51.19 9.5,51.19 10.36,50.33 22.58,50.33 21.24,48.99 21.24,47.11 12.05,47.11 11.34,46.81 11.04,46.1 11.17,45.6 11.54,45.23 11.54,40.57 11.08,39.44 12.05,38.69 14.34,38.69 14.34,38.6 15.55,37.39 16.76,38.6 16.76,38.69 21.24,38.69 21.24,35.83
AUD_AGND on L5GND: 11.48,19.19 10.73,19.94 10.73,25.17 10.92,25.36 11.66,25.36 12.01,25 13.87,25 13.98,24.89 13.98,20.96 12.21,19.19
RING2_HPMIC1 on TOP: 7.57,34.97 7.42,35.13 7.42,36.88 6.98,37.31 6.98,38.33 7.16,38.5 8.97,38.5 9.35,38.12 9.35,36.83 8.41,35.89 8.41,35.03 8.36,34.97 ; 2 cut-outs
RING2_R on BOTTOM: 11.14,20.6 10.85,20.89 10.85,21.49 11.3,21.94 13.94,21.94 13.99,21.89 13.99,20.65 13.94,20.6
SLEEVE_HPMIC1 on TOP: 7.44,46.46 7.34,46.56 7.34,48.11 7.68,48.45 8.46,48.45 8.78,48.77 8.78,50.18 8.94,50.34 10.13,50.34 10.29,50.19 10.29,48 8.74,46.46 ; 2 cut-outs
SLEEVE_R on TOP: 4.98,46.38 4.44,46.91 4.44,47.95 4.77,48.28 5.82,48.28 6.45,48.92 6.98,48.92 7.11,48.79 7.11,46.71 6.78,46.38 ; 1 cut-out
SLEEVE_R on BOTTOM: 11.07,22.07 10.88,22.26 10.88,23.17 11.13,23.42 11.15,23.42 11.2,23.47 13.89,23.47 13.99,23.37 13.99,22.15 13.92,22.07 11.07,22.07
USB20_VCCA on TOP: 1.63,45.79 1.6,45.82 1.6,51.13 1.73,51.26 2.67,51.26 2.79,51.38 2.79,54.35 3.5,55.07 3.5,55.62 4.06,56.18 4.06,57.15 5.44,58.52 6.6,58.52 6.71,58.42 6.71,57.96 6.55,57.81 5.54,57.81 5,57.28 5,55.32 5.13,55.19 6.93,55.19 8.61,56.87 9.93,56.87 10.64,56.16 10.64,53.95 9.83,53.14 6.1,53.14 5.89,52.93 5.89,51.61 5.41,51.13 4.62,51.13 4.29,50.8 4.29,48.79 3.35,47.85 3.35,46.05 3.1,45.79 ; 15 cut-outs
USB20_VCCA on BOTTOM: 9.3,27.02 9.17,27.15 9.17,28.93 9.37,29.13 12.27,29.13 12.47,28.93 13.87,28.93 13.99,28.8 13.99,27.15 13.87,27.02
USB20_VCCA on L3: 1.63,46.58 3.96,46.58 4.32,46.23 4.32,36.85 6.1,35.08 6.1,31.72 8.48,29.34 10.67,29.34 10.9,29.11 10.9,27.51 10.46,27.07 7.8,27.07 4.01,30.86 4.01,33.91 2.34,35.58 2.34,42.42 1.47,43.28 1.47,46.43

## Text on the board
Ref Des/Silkscreen Bottom: M.I.T. | PJTM5 | 17A61-1 | Vegas MLK KBL-R IO Board
User.36: Board Accuracy Check,Sep 26 15:06:50 2017,Passed | Dummy-Static-No Shape On Layer Check,Sep 26 15:06:51 2017,Passed | LF HASL Via Check,Jun 21 11:00:03 2017,220 errors | Split Plane Check,Jun 21 11:22:56 2017,Passed | Via Aspect Ratio Check,Jun 21 11:00:05 2017,4 errors | Via Check,Jun 21 11:00:05 2017,5 errors | Via Connectivity,Jun 21 11:00:05 2017,17 errors | Via On Moat Check,Jun 21 11:00:04 2017,18 errors | Via On Pad Check,Jun 21 11:00:03 2017,5 errors | Via To Via Per Net Check,Jun 21 11:00:05 2017,Warning | Via To Via Spacing Check,Jun 21 11:00:05 2017,83 errors | Via Type Check,Jun 21 11:00:05 2017,5 errors
User.39: ByImpedance:100.0@_REF_L2=("3.5/9.5(L1/L3)")|_REF_L1=("4.0/4.5(L2)")|_REF_L6=("4.0/4.5(L5)")|Type="DP"|_REF_L4=("3.5/5.5(L3/L5)" "4.0/6.0(L2/L5)")|_REF_L3=("4.0/6.0(L2/L5)")|imp="100.0" | ByImpedance:37.5@_REF_L2=("7.0(L1/L3)")|_REF_L1=("13.0(L2)")|_REF_L6=("13.0(L5)")|Type="SE"|_REF_L4=("11.5(L2/L5)" "11.0(L3/L5)")|_REF_L3=("11.5(L2/L5)")|imp="37.5" | ByImpedance:40.0@_REF_L2=("6.0(L1/L3)")|_REF_L1=("11.5(L2)")|_REF_L6=("11.5(L5)")|Type="SE"|_REF_L4=("10.5(L2/L5)" "10.0(L3/L5)")|_REF_L3=("10.5(L2/L5)")|imp="40.0" | ByImpedance:42.0@_REF_L2=("5.5(L1/L3)")|_REF_L1=("11.0(L2)")|_REF_L6=("11.0(L5)")|Type="SE"|_REF_L4=("9.0(L3/L5)" "9.5(L2/L5)")|_REF_L3=("9.5(L2/L5)")|imp="42.0" | ByImpedance:45.0@_REF_L2=("5.0(L1/L3)")|_REF_L1=("9.0(L2)")|_REF_L6=("9.0(L5)")|Type="SE"|_REF_L4=("8.0(L2/L5)" "8.0(L3/L5)")|_REF_L3=("8.0(L2/L5)")|imp="45.0" | ByImpedance:50.0@_REF_L2=("3.5(L1/L3)")|_REF_L1=("7.5(L2)")|_REF_L6=("7.5(L5)")|Type="SE"|_REF_L4=("6.5(L2/L5)" "6.5(L3/L5)")|_REF_L3=("6.5(L2/L5)")|imp="50.0" | ByImpedance:55.0@_REF_L1=("6.0(L2)")|_REF_L6=("6.0(L5)")|Type="SE"|_REF_L4=("5.0(L3/L5)" "5.0(L2/L5)")|_REF_L3=("5.0(L2/L5)")|imp="55.0" | ByImpedance:70.0@_REF_L2=("6.0/4.0(L1/L3)")|_REF_L1=("11.0/5.0(L2)")|_REF_L6=("11.0/5.0(L5)")|Type="DP"|_REF_L4=("9.0/5.0(L2/L5)" "8.0/4.0(L3/L5)")|_REF_L3=("9.0/5.0(L2/L5)")|imp="70.0" | ByImpedance:80.0@_REF_L2=("4.5/4.0(L1/L3)")|_REF_L1=("8.0/5.0(L2)")|_REF_L6=("8.0/5.0(L5)")|Type="DP"|_REF_L4=("5.5/4.0(L3/L5)" "6.5/5.0(L2/L5)")|_REF_L3=("6.5/5.0(L2/L5)")|imp="80.0" | ByImpedance:83.0@_REF_L2=("4.0/4.0(L1/L3)")|_REF_L1=("7.5/5.5(L2)")|_REF_L6=("7.5/5.5(L5)")|Type="DP"|_REF_L4=("6.0/5.0(L2/L5)" "6.0/5.0(L3/L5)")|_REF_L3=("6.0/5.0(L2/L5)")|imp="83.0" | ByImpedance:85.0@_REF_L2=("4.0/4.5(L1/L3)")|_REF_L1=("7.0/5.0(L2)")|_REF_L6=("7.0/5.0(L5)")|Type="DP"|_REF_L4=("5.0/4.5(L3/L5)" "6.0/5.5(L2/L5)")|_REF_L3=("6.0/5.5(L2/L5)")|imp="85.0" | ByImpedance:88.0@_REF_L2=("3.5/4.0(L1/L3)")|_REF_L1=("6.0/4.5(L2)")|_REF_L6=("6.0/4.5(L5)")|Type="DP"|_REF_L4=("4.5/4.5(L3/L5)" "6.0/6.5(L2/L5)")|_REF_L3=("6.0/6.5(L2/L5)")|imp="88.0" | ByImpedance:90.0@_REF_L2=("3.5/4.5(L1/L3)")|_REF_L1=("6.0/5.0(L2)")|_REF_L6=("6.0/5.0(L5)")|Type="DP"|_REF_L4=("6.0/7.5(L2/L5)" "4.0/4.0(L3/L5)")|_REF_L3=("6.0/7.5(L2/L5)")|imp="90.0" | LayerIndex:nil | Source:6-1.2-17a.xls | artWorks:("_REF_L3" "_REF_L4" "_REF_L2" "_REF_L6" "_REF_L1") | gtImpOutlineUsed:BOARD GEOMETRY/OUTLINE
User.43: This gerber is just for your reference to find the DP impedance traces in layer L1. | DP IMPEDANCE TABLE: L1 | * - Denotes that this Impedance | is NOT used | IMP(Ohm) | *70.0 | *80.0 | *83.0 | 85.0 | *88.0 | *90.0 | *100.0 | WIDTH(mils) | 11.0/5.0 | 8.0/5.0 | 7.5/5.5 | 7.0/5.0 | 6.0/4.5 | 6.0/5.0 | 4.0/4.5 | TYPE | DP | Ref. Plane | L2
User.45: Note:Refer to DRILL layer for ELLIPSE drill direction | FIGURE | SIZE | 10.0 | 16.0 | 34.0 | 46.0 | 65.0 | 103.0 | 48.0x24.0 | 52.0x24.0 | 67.0x40.0 | 130.0x24.0 | 134.0x103.0 | DRILL CHART: TOP to BOTTOM | ALL UNITS ARE IN MILS | PLATED | NON-PLATED | QTY | 225 | 11 | 4 | 1 | 6 | 2 | This gerber is just for your reference to find the SE impedance traces in layer L1. | This gerber is just for your reference to find the SE impedance traces in layer L2. | This gerber is just for your reference to find the SE impedance traces in layer L3. | This gerber is just for your reference to find the SE impedance traces in layer L6. | This gerber is just for your reference to find the DP impedance traces in layer L2. | This gerber is just for your reference to find the DP impedance traces in layer L3. | This gerber is just for your reference to find the DP impedance traces in layer L6. | This gerber is just for your reference to find the SE impedance traces in layer L4. | This gerber is just for your reference to find the DP impedance traces in layer L4. | DP IMPEDANCE TABLE: L2 | DP IMPEDANCE TABLE: L3 | DP IMPEDANCE TABLE: L4 | DP IMPEDANCE TABLE: L6 | SE IMPEDANCE TABLE: L1 | SE IMPEDANCE TABLE: L2 | SE IMPEDANCE TABLE: L3 | SE IMPEDANCE TABLE: L4 | SE IMPEDANCE TABLE: L6 | * - Denotes that this Impedance | is NOT used | Model | Vegas MLK KBL-R IO Board | PCB_NO | 17A61 | VER. | IMP(Ohm) | *37.5 | *70.0 | *40.0 | *80.0 | *42.0 | *83.0 | *45.0 | *85.0 | 85.0 | *50.0 | *88.0 | 50.0 | *55.0 | *90.0 | *100.0 | Layer | DRILL | L1 | L2VCC | L3 | TMASK | TPLACE | TSILK | TSMD | WIDTH(mils) | 13.0 | 7.0 | 11.5 | 6.0 | 11.0 | 5.5 | 5.0 | 9.0 | 3.5 | 7.5 | 10.5 | 9.5 | 8.0 | 6.5 | 11.0/5.0 | 8.0/5.0 | 7.5/5.5 | 7.0/5.0 | 6.0/4.5 | 6.0/5.0 | 4.0/4.5 | Designer | MOSSE | 6.0/4.0 | 9.0/5.0 | 4.5/4.0 | 6.5/5.0 | 8.0/4.0 | 4.0/4.0 | 5.5/4.0 | 6.0/5.5 | 3.5/4.0 | 6.0/6.5 | 3.5/4.5 | 6.0/7.5 | 3.5/9.5 | 4.0/6.0 | 5.0/4.5 | 4.5/4.5 | 3.5/5.5 | TYPE | SE | DP | Date | 11/10/2017 | Ref. Plane | L1/L3 | L2 | L5 | L2/L5 | L3/L5 | BMASK | BPLACE | BSILK | BSMD | L4 | L5GND | L6
